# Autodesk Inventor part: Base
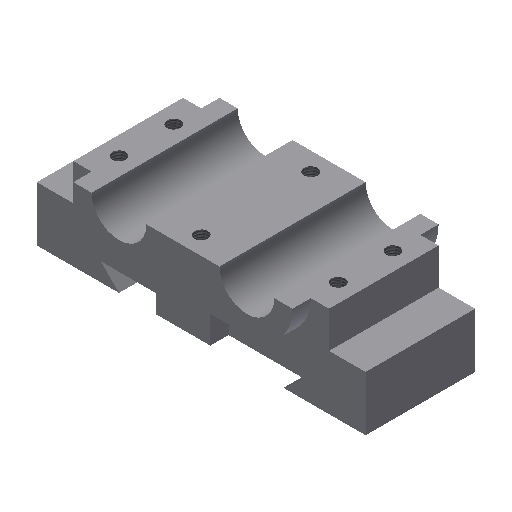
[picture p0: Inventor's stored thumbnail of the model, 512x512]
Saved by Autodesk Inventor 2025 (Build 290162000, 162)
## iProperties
Shininess: 77.0
Length Units: 11269
Angle Units: 11279
Time Units: 11290
Mass Units: 11283
Length Display Precision: 3
Angle Display Precision: 2
Created: 2002-02
Part Number: Base
Document SubType Name: Modeling
Designer: ***
Density: 1 g/cm^3
Material: Generic
Appearance: Default
Density: 0.0
Volumn: 0.0
Area: 0.0
PropertySet Name: Model Information
Control State: 0
Master: False
Checked Out: False
Author: ***
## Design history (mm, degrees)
sketch "Sketch2"
  geometry: L1 (-10.066, -1.263)-(24.934, -1.263); L2 (37.434, 11.237)-(32.434, 11.237); L3 (17.434, 11.237)-(-2.566, 11.237); L4 (-17.566, 11.237)-(-22.566, 11.237); A1 r 12.5 centre (-10.066, 11.237) between (-22.566, 11.237) and (-10.066, -1.263); A2 r 12.5 centre (24.934, 11.237) between (24.934, -1.263) and (37.434, 11.237); A3 r 7.5 centre (24.934, 11.237) between (17.434, 11.237) and (32.434, 11.237); A4 r 7.5 centre (-10.066, 11.237) between (-17.566, 11.237) and (-2.566, 11.237)
  constraints: 8 end point, 8 point on circle, 4 centre point, 3 horizontal, 3 parallel, 2 coincident, 2 equal radius, 2 tangent
  dimensions: "d0" = 12.5 radius of A1; "d1" = 7.5 radius of A4; "d2" = 35 distance of A1.centre A2.centre; "d3" = 12.5 distance between parallel lines of L3 L1
extrude "Extrusion1" new body sketch "Sketch2" stored distance "d4" = 40; taper "d5" = 0 deg
sketch "Sketch4"
  geometry: L1 (-27.566, 1.237)-(-37.566, 1.237); L2 (-37.566, 1.237)-(-37.566, -13.763); L3 (-37.566, -13.763)-(-15.066, -13.763); L4 (-15.066, -13.763)-(-20.066, -8.763); L5 (-20.066, -8.763)-(34.934, -8.763); L6 (34.934, -8.763)-(29.934, -13.763); L7 (29.934, -13.763)-(52.434, -13.763); L8 (52.434, -13.763)-(52.434, 1.237); L9 (52.434, 1.237)-(42.434, 1.237); L10 (24.934, -1.263)-(-10.066, -1.263); L11 (-17.566, 11.237)-(-22.566, 11.237) reference; L12 (37.434, 11.237)-(32.434, 11.237) reference; L13 (-22.566, 11.237)-(-27.566, 11.237); L14 (-27.566, 11.237)-(-27.566, 1.237); L15 (37.434, 11.237)-(42.434, 11.237); L16 (42.434, 11.237)-(42.434, 1.237); A1 r 12.5 centre (24.934, 11.237) between (24.934, -1.263) and (37.434, 11.237); A2 r 12.5 centre (-10.066, 11.237) between (-22.566, 11.237) and (-10.066, -1.263); A3 r 12.5 centre (24.934, 11.237) between (24.934, -1.263) and (37.434, 11.237) reference; A4 r 12.5 centre (-10.066, 11.237) between (-22.566, 11.237) and (-10.066, -1.263) reference
  constraints: 28 end point, 6 perpendicular, 5 equal length, 4 concentric, 4 parallel, 4 point on circle, 2 centre point, 2 collinear, 1 tangent
  dimensions: "d12" = 15 distance of L1.end L2.end; "d13" = 25 distance from line of L3 L11.end; "d14" = 90 distance between parallel lines of L2 L8; "d15" = 5 distance between parallel lines of L5 L7; "d16" = 22.5 distance of L2.end L3.end; "d24" = 5 distance of L12.start L15.end; "d25" = 15 distance from line of L8 L12.start
extrude "Extrusion3" join sketch "Sketch4" stored distance "d17" = 30; taper "d18" = 0 deg
sketch "Sketch5"
  geometry: L1 (-14.934, -1.263)-(0.066, -1.263); L2 (0.066, -1.263)-(0.066, -8.763); L3 (0.066, -8.763)-(-14.934, -8.763); L4 (-14.934, -8.763)-(-14.934, -1.263); L5 (10.066, -1.263)-(-24.934, -1.263) reference; 1 further point
  constraints: 8 end point, 2 parallel, 1 collinear, 1 horizontal, 1 perpendicular
  dimensions: "d19" = 7.5 distance of L1.end L2.end; "d20" = 15 distance of L2.end L3.end; "d21" = 15 distance from line of point (-29.934, -13.763) L4
extrude "Extrusion4" join sketch "Sketch5" distance "d22" = 40; taper "d23" = 0 deg
sketch "Sketch6"
  geometry: L1 (-5, -35)-(0, -35) reference; L2 (-5, -35)-(-5, -5) reference; 1 further point
  dimensions: "d26" = 7.5 distance from line of L1 point (0, -27.5); "d27" = 5 distance from line of L2 point (0, -27.5)
hole "Hole1" sketch "Sketch6" diameter "d28" = 3.688; stored, may be unused: countersink angle "d32" = 82 deg, drill point angle "d34" = 0 deg; dims "d29" = 9, "d30" = 4, "d31" = 2, "d33" = 15
pattern_linear "Rectangular Pattern1" dims "d40" = 15
sketch "Sketch7"
  geometry: L1 (-20, -40)-(-20, -35) reference; L2 (0, -40)-(20, -40) reference; 1 further point
  dimensions: "d41" = 30 distance from line of L1 point (10, -35); "d42" = 5 distance from line of L2 point (10, -35)
hole "Hole2" sketch "Sketch7" diameter "d43" = 3.688; stored, may be unused: countersink angle "d47" = 82 deg, drill point angle "d49" = 0 deg; dims "d44" = 9, "d45" = 4, "d46" = 2, "d48" = 15
pattern_linear "Rectangular Pattern2"
body "Solid1"
